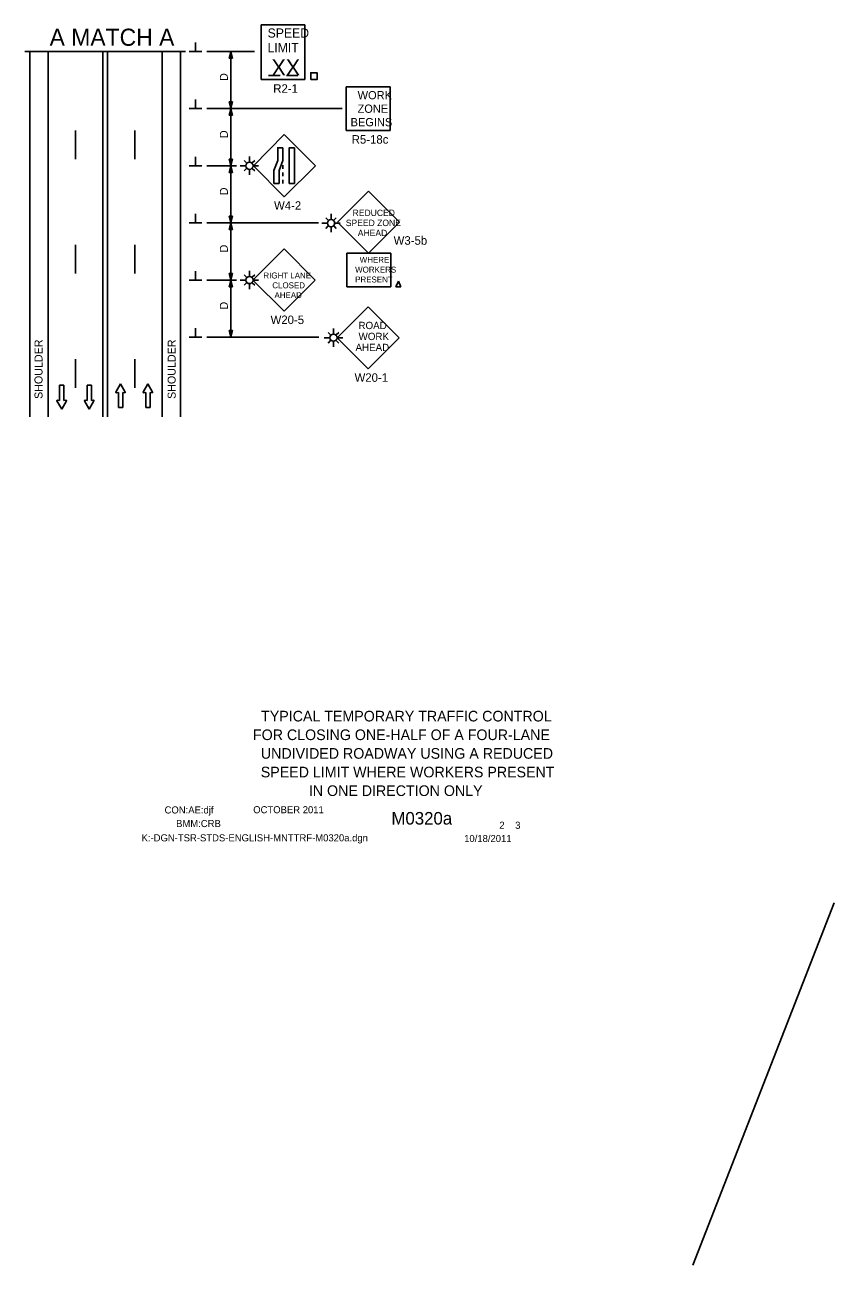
# Model space of a CAD drawing. Extents: x 16473 to 19504, y 4850 to 6923.
# Drawn here: x 17997 to 18706, y 5563 to 6648 of the extents above; entities that cross this region are included whole.
import ezdxf

# ---------------------------------------------------------------- set-up
doc = ezdxf.new("R2010")
doc.units = 0
for name, color, linetype in [('ALI_LEGAL_EX', 7, 'Continuous'), ('BORDER_SIGNAL_WO', 7, 'Continuous'), ('MT_SCRATCH_LEVEL_E', 7, 'Continuous'), ('PAVT_EDGE_EX', 7, 'Continuous'), ('TRAFFIC_SIGNS_PR', 7, 'Continuous'), ('TYPICAL_TEXT_DIMEN_PR', 7, 'Continuous')]:
    doc.layers.add(name, color=color, linetype=linetype)

msp = doc.modelspace()

# ---------------------------------------------------------------- linework, layer by layer
at = {"layer": 'ALI_LEGAL_EX'}
for points in [[(18041.7, 6555.4), (18041.7, 6530.4)], [(18093.7, 6555.4), (18093.7, 6530.4)], [(18041.7, 6455.4), (18041.7, 6430.4)], [(18093.7, 6455.4), (18093.7, 6430.4)], [(18041.7, 6355.4), (18041.7, 6330.4)], [(18093.7, 6355.4), (18093.7, 6330.4)]]:
    msp.add_lwpolyline(points, dxfattribs=at)
at = {"layer": 'MT_SCRATCH_LEVEL_E'}
for p, q in [((18031.5, 6332.7), (18027.8, 6332.7)), ((18027.8, 6332.7), (18027.8, 6319.4)), ((18031.5, 6332.7), (18027.8, 6332.7)), ((18027.8, 6332.7), (18027.8, 6319.4)), ((18031.5, 6319.4), (18031.5, 6332.7)), ((18031.5, 6319.4), (18031.5, 6332.7)), ((18055.7, 6332.7), (18051.9, 6332.7)), ((18051.9, 6332.7), (18051.9, 6319.4)), ((18055.7, 6332.7), (18051.9, 6332.7)), ((18051.9, 6332.7), (18051.9, 6319.4)), ((18055.7, 6319.4), (18055.7, 6332.7)), ((18055.7, 6319.4), (18055.7, 6332.7)), ((18081.2, 6333.9), (18077.1, 6326.7)), ((18081.2, 6333.9), (18077.1, 6326.7)), ((18077.5, 6326), (18079.3, 6326.3)), ((18077.5, 6326), (18079.3, 6326.3)), ((18079.3, 6326.3), (18079.3, 6313.1)), ((18079.3, 6326.3), (18079.3, 6313.1)), ((18085.3, 6326.7), (18081.2, 6333.9)), ((18085.3, 6326.7), (18081.2, 6333.9)), ((18083.1, 6313.1), (18083.1, 6326.3)), ((18083.1, 6326.3), (18084.8, 6326)), ((18083.1, 6313.1), (18083.1, 6326.3)), ((18083.1, 6326.3), (18084.8, 6326)), ((18105.1, 6333.9), (18101, 6326.7)), ((18105.1, 6333.9), (18101, 6326.7)), ((18101.5, 6326), (18103.3, 6326.3)), ((18101.5, 6326), (18103.3, 6326.3)), ((18103.3, 6326.3), (18103.3, 6313.1)), ((18103.3, 6326.3), (18103.3, 6313.1)), ((18109.2, 6326.7), (18105.1, 6333.9)), ((18109.2, 6326.7), (18105.1, 6333.9)), ((18107, 6313.1), (18107, 6326.3)), ((18107, 6326.3), (18108.8, 6326)), ((18107, 6313.1), (18107, 6326.3)), ((18107, 6326.3), (18108.8, 6326)), ((18025.5, 6319), (18029.7, 6311.8)), ((18025.5, 6319), (18029.7, 6311.8)), ((18027.8, 6319.4), (18026, 6319.7)), ((18027.8, 6319.4), (18026, 6319.7)), ((18029.7, 6311.8), (18033.8, 6319)), ((18029.7, 6311.8), (18033.8, 6319)), ((18033.3, 6319.7), (18031.5, 6319.4)), ((18033.3, 6319.7), (18031.5, 6319.4)), ((18049.7, 6319), (18053.8, 6311.8)), ((18049.7, 6319), (18053.8, 6311.8)), ((18051.9, 6319.4), (18050.2, 6319.7)), ((18051.9, 6319.4), (18050.2, 6319.7)), ((18053.8, 6311.8), (18057.9, 6319)), ((18053.8, 6311.8), (18057.9, 6319)), ((18057.5, 6319.7), (18055.7, 6319.4)), ((18057.5, 6319.7), (18055.7, 6319.4)), ((18079.3, 6313.1), (18083.1, 6313.1)), ((18079.3, 6313.1), (18083.1, 6313.1)), ((18103.3, 6313.1), (18107, 6313.1)), ((18103.3, 6313.1), (18107, 6313.1))]:
    msp.add_line(p, q, dxfattribs=at)
for centre, start, end in [((18077.5, 6326.5), 150.4248, 279.9638), ((18077.5, 6326.5), 150.4248, 279.9638), ((18084.9, 6326.5), 260.0362, 29.7731), ((18084.9, 6326.5), 260.0362, 29.7731), ((18101.4, 6326.5), 150.4248, 279.9638), ((18101.4, 6326.5), 150.4248, 279.9638), ((18108.8, 6326.5), 260.0362, 29.7731), ((18108.8, 6326.5), 260.0362, 29.7731), ((18025.9, 6319.2), 80.0362, 209.7731), ((18025.9, 6319.2), 80.0362, 209.7731), ((18033.4, 6319.2), 330.4248, 99.9638), ((18033.4, 6319.2), 330.4248, 99.9638), ((18050.1, 6319.2), 80.0362, 209.7731), ((18050.1, 6319.2), 80.0362, 209.7731), ((18057.5, 6319.2), 330.4248, 99.9638), ((18057.5, 6319.2), 330.4248, 99.9638)]:
    msp.add_arc(centre, 0.463, start, end, dxfattribs=at)
at = {"layer": 'PAVT_EDGE_EX'}
for p, q in [((18001.7, 6624.7), (18001.7, 6305.2)), ((18017.7, 6624.7), (18017.7, 6305.2)), ((18065.7, 6624.7), (18065.7, 6305.2)), ((18069.7, 6624.7), (18069.7, 6305.2)), ((18117.7, 6624.7), (18117.7, 6305.2)), ((18133.7, 6624.7), (18133.7, 6305.2))]:
    msp.add_line(p, q, dxfattribs=at)
at = {"layer": 'TRAFFIC_SIGNS_PR'}
for p, q in [((18204.2, 6648), (18242.6, 6648)), ((18204.2, 6600), (18204.2, 6648)), ((18204.2, 6648), (18242.6, 6648)), ((18204.2, 6600), (18204.2, 6648)), ((18242.6, 6600), (18242.6, 6648)), ((18242.6, 6600), (18242.6, 6648)), ((18204.2, 6600), (18242.6, 6600)), ((18204.2, 6600), (18242.6, 6600)), ((18210.8, 6603.6), (18220.9, 6603.6)), ((18226.3, 6603.6), (18236.3, 6603.6)), ((18278.7, 6555.4), (18278.7, 6593.8)), ((18278.7, 6593.8), (18317.1, 6593.8)), ((18317.1, 6555.4), (18317.1, 6593.8)), ((18278.7, 6555.4), (18317.1, 6555.4)), ((18224.5, 6551.9), (18197.4, 6524.7)), ((18251.7, 6524.7), (18224.5, 6551.9)), ((18194, 6528.3), (18194, 6532.8)), ((18190.8, 6524.7), (18186, 6524.7)), ((18191.5, 6527.2), (18189.4, 6529.3)), ((18191.5, 6522.2), (18189.4, 6520.1)), ((18194, 6516.8), (18194, 6521.2)), ((18196.5, 6527.2), (18198.6, 6529.3)), ((18196.5, 6522.2), (18198.6, 6520.1)), ((18197.1, 6524.7), (18202, 6524.7)), ((18197.4, 6524.7), (18224.5, 6497.6)), ((18223.3, 6525.2), (18223.3, 6522)), ((18224.5, 6497.6), (18251.7, 6524.7)), ((18223.3, 6518.8), (18223.3, 6515.6)), ((18223.3, 6512.4), (18223.3, 6509.2)), ((18298.2, 6502.6), (18271.1, 6475.4)), ((18325.4, 6475.4), (18298.2, 6502.6)), ((18262.9, 6477.1), (18260.7, 6479.2)), ((18265.4, 6478.1), (18265.4, 6482.6)), ((18267.9, 6477.1), (18270, 6479.2)), ((18262.2, 6474.5), (18257.4, 6474.5)), ((18262.9, 6472), (18260.7, 6469.9)), ((18265.4, 6466.6), (18265.4, 6471)), ((18267.9, 6472), (18270, 6469.9)), ((18268.5, 6474.5), (18273.4, 6474.5)), ((18271.1, 6475.4), (18298.2, 6448.2)), ((18298.2, 6448.2), (18325.4, 6475.4)), ((18224.3, 6451.9), (18197.1, 6424.7)), ((18251.4, 6424.7), (18224.3, 6451.9)), ((18279.2, 6448.1), (18317.6, 6448.1)), ((18279.2, 6418.8), (18279.2, 6448.1)), ((18317.6, 6418.8), (18317.6, 6448.1)), ((18190.8, 6424.7), (18186, 6424.7)), ((18191.5, 6427.3), (18189.4, 6429.4)), ((18194, 6428.3), (18194, 6432.8)), ((18196.5, 6427.3), (18198.6, 6429.4)), ((18197.1, 6424.7), (18202, 6424.7)), ((18197.1, 6424.7), (18224.3, 6397.6)), ((18224.3, 6397.6), (18251.4, 6424.7)), ((18191.5, 6422.2), (18189.4, 6420.1)), ((18194, 6416.8), (18194, 6421.2)), ((18196.5, 6422.2), (18198.6, 6420.1)), ((18279.2, 6418.8), (18317.6, 6418.8)), ((18297.8, 6401.4), (18270.7, 6374.3)), ((18325, 6374.3), (18297.8, 6401.4)), ((18267.5, 6377.8), (18267.5, 6382.3)), ((18264.4, 6374.3), (18259.5, 6374.3)), ((18265, 6376.8), (18262.9, 6378.9)), ((18265, 6371.7), (18262.9, 6369.6)), ((18267.5, 6366.3), (18267.5, 6370.7)), ((18270, 6376.8), (18272.1, 6378.9)), ((18270, 6371.7), (18272.1, 6369.6)), ((18270.7, 6374.3), (18297.8, 6347.1)), ((18270.7, 6374.3), (18275.6, 6374.3)), ((18297.8, 6347.1), (18325, 6374.3))]:
    msp.add_line(p, q, dxfattribs=at)
for points in [[(18247.6, 6600), (18253.2, 6600), (18253.2, 6606.1), (18247.6, 6606.1)], [(18223.3, 6540.5), (18223.3, 6529.3), (18219.9, 6520.4), (18219.9, 6509.2), (18215.4, 6509.2), (18215.4, 6520.4), (18218.8, 6529.3), (18218.8, 6540.5)], [(18233.4, 6540.5), (18233.4, 6509.2), (18228.9, 6509.2), (18228.9, 6540.5)]]:
    msp.add_lwpolyline(points, close=True, dxfattribs=at)
for points in [[(18324.3, 6423.8), (18322.1, 6418.8)], [(18322.1, 6418.8), (18324.3, 6423.8)], [(18326.5, 6418.8), (18324.3, 6423.8)], [(18324.3, 6423.8), (18326.5, 6418.8)], [(18322.1, 6418.8), (18326.5, 6418.8)], [(18326.5, 6418.8), (18322.1, 6418.8)]]:
    msp.add_lwpolyline(points, dxfattribs=at)
for centre in [(18194, 6524.7), (18265.4, 6474.5), (18194, 6424.7), (18267.5, 6374.3)]:
    msp.add_circle(centre, 3.15, dxfattribs=at)
at = {"layer": 'TYPICAL_TEXT_DIMEN_PR'}
for p, q in [((18146.8, 6624.7), (18146.8, 6632.5)), ((17997.4, 6624.7), (18138, 6624.7)), ((18152.4, 6624.7), (18141.2, 6624.7)), ((18198.3, 6624.7), (18156.7, 6624.7)), ((18176.1, 6618.8), (18177.7, 6624.7)), ((18177.7, 6618.8), (18176.1, 6618.8)), ((18177.7, 6624.7), (18177.7, 6574.7)), ((18177.7, 6624.7), (18179.3, 6618.8)), ((18179.3, 6618.8), (18177.7, 6618.8)), ((18146.8, 6574.7), (18146.8, 6582.5)), ((18177.7, 6574.7), (18176.1, 6580.5)), ((18176.1, 6580.5), (18177.7, 6580.5)), ((18177.7, 6580.5), (18179.3, 6580.5)), ((18179.3, 6580.5), (18177.7, 6574.7)), ((18152.4, 6574.7), (18141.2, 6574.7)), ((18275.2, 6574.7), (18156.7, 6574.7)), ((18176.1, 6568.8), (18177.7, 6574.7)), ((18177.7, 6568.8), (18176.1, 6568.8)), ((18177.7, 6574.7), (18179.3, 6568.8)), ((18177.7, 6574.7), (18177.7, 6524.7)), ((18179.3, 6568.8), (18177.7, 6568.8)), ((18146.8, 6524.7), (18146.8, 6532.5)), ((18152.4, 6524.7), (18141.2, 6524.7)), ((18182.7, 6524.7), (18156.7, 6524.7)), ((18177.7, 6524.7), (18176.1, 6530.5)), ((18176.1, 6530.5), (18177.7, 6530.5)), ((18176.1, 6518.8), (18177.7, 6524.7)), ((18177.7, 6530.5), (18179.3, 6530.5)), ((18179.3, 6530.5), (18177.7, 6524.7)), ((18177.7, 6524.7), (18177.7, 6474.7)), ((18177.7, 6524.7), (18179.3, 6518.8)), ((18177.7, 6518.8), (18176.1, 6518.8)), ((18179.3, 6518.8), (18177.7, 6518.8)), ((18146.8, 6474.7), (18146.8, 6482.5)), ((18177.7, 6474.7), (18176.1, 6480.5)), ((18176.1, 6480.5), (18177.7, 6480.5)), ((18177.7, 6480.5), (18179.3, 6480.5)), ((18179.3, 6480.5), (18177.7, 6474.7)), ((18152.4, 6474.7), (18141.2, 6474.7)), ((18254.3, 6474.7), (18156.7, 6474.7)), ((18176.1, 6468.8), (18177.7, 6474.7)), ((18177.7, 6468.8), (18176.1, 6468.8)), ((18177.7, 6474.7), (18177.7, 6424.7)), ((18177.7, 6474.7), (18179.3, 6468.8)), ((18179.3, 6468.8), (18177.7, 6468.8)), ((18152.4, 6424.7), (18141.2, 6424.7)), ((18146.8, 6424.7), (18146.8, 6432.5)), ((18182.7, 6424.7), (18156.7, 6424.7)), ((18177.7, 6424.7), (18176.1, 6430.5)), ((18176.1, 6430.5), (18177.7, 6430.5)), ((18176.1, 6418.8), (18177.7, 6424.7)), ((18177.7, 6430.5), (18179.3, 6430.5)), ((18179.3, 6430.5), (18177.7, 6424.7)), ((18177.7, 6424.7), (18177.7, 6374.7)), ((18177.7, 6424.7), (18179.3, 6418.8)), ((18177.7, 6418.8), (18176.1, 6418.8)), ((18179.3, 6418.8), (18177.7, 6418.8)), ((18146.8, 6374.7), (18146.8, 6382.5)), ((18177.7, 6374.7), (18176.1, 6380.5)), ((18176.1, 6380.5), (18177.7, 6380.5)), ((18177.7, 6380.5), (18179.3, 6380.5)), ((18179.3, 6380.5), (18177.7, 6374.7)), ((18152.4, 6374.7), (18141.2, 6374.7)), ((18254.8, 6374.7), (18156.7, 6374.7)), ((18705.8, 5880), (18582.1, 5563))]:
    msp.add_line(p, q, dxfattribs=at)

# ---------------------------------------------------------------- texts
at = {"layer": 'BORDER_SIGNAL_WO'}
for s, height, p in [('TYPICAL TEMPORARY TRAFFIC CONTROL', 9.3, (18204.2, 6038.6)), ('FOR CLOSING ONE-HALF OF A FOUR-LANE', 9.3, (18197.1, 6022.3)), ('UNDIVIDED ROADWAY USING A REDUCED', 9.3, (18204, 6006)), ('SPEED LIMIT WHERE WORKERS PRESENT', 9.3, (18203.9, 5989.7)), ('IN ONE DIRECTION ONLY', 9.3, (18246, 5973.4)), ('CON:AE:djf', 6.2, (18119.7, 5958.1)), ('    OCTOBER 2011    ', 6.2, (18188.1, 5958.3)), ('    M0320a   ', 11, (18301.9, 5948.4)), ('BMM:CRB   ', 6.2, (18129.8, 5946.2)), (' 2    3 ', 6.2, (18410.4, 5944.7)), ('K:-DGN-TSR-STDS-ENGLISH-MNTTRF-M0320a.dgn        ', 6.2, (18099.6, 5933.7)), ('10/18/2011    ', 6.2, (18381.9, 5933.1))]:
    msp.add_text(s, height=height, dxfattribs=at).set_placement(p)
at = {"layer": 'TRAFFIC_SIGNS_PR'}
for s, height, p in [('SPEED', 8, (18209.9, 6636.8)), ('SPEED', 8, (18209.9, 6636.8)), ('LIMIT', 8, (18209.8, 6624)), ('LIMIT', 8, (18209.8, 6624)), ('XX', 14.03, (18213.3, 6603.7)), ('R2-1', 7.44, (18214.9, 6588.5)), ('R2-1', 7.44, (18214.8, 6588.5)), ('WORK', 7.22, (18288.7, 6582.8)), ('ZONE', 7.22, (18288.6, 6571)), ('BEGINS', 7.22, (18282.5, 6559.2)), ('R5-18c', 7.44, (18283.5, 6544)), ('W4-2', 7.44, (18215.5, 6486.2)), ('SPEED ZONE', 5.6, (18278.3, 6471.9)), ('REDUCED', 5.6, (18284.3, 6480.7)), ('AHEAD', 5.6, (18288.8, 6463.1)), ('W3-5b', 7.44, (18320.2, 6455.6)), ('WHERE', 5.2, (18290.5, 6439.8)), ('WORKERS', 5.2, (18286.5, 6431.2)), ('RIGHT LANE', 5.2, (18206.2, 6426.1)), ('PRESENT', 5.2, (18286.5, 6422.6)), ('CLOSED', 5.2, (18214, 6417.5)), ('AHEAD', 5.2, (18215.9, 6408.9)), ('W20-5', 7.44, (18212.5, 6386.2)), ('ROAD', 6.4, (18289.4, 6381.8)), ('AHEAD', 6.4, (18286.8, 6362.6)), ('WORK', 6.4, (18289.5, 6372.2)), ('W20-1', 7.44, (18286, 6335.7))]:
    msp.add_text(s, height=height, dxfattribs=at).set_placement(p)
at = {"layer": 'TYPICAL_TEXT_DIMEN_PR'}
msp.add_text('A MATCH A', height=15, dxfattribs=at).set_placement((18019.1, 6629.6))
for s, p in [('D', (18175.1, 6598.9)), ('D', (18175.1, 6548.9)), ('D', (18175.1, 6498.9)), ('D', (18175.1, 6448.9)), ('D', (18175.1, 6398.9)), ('SHOULDER', (18012.9, 6320.7)), ('SHOULDER', (18129.4, 6320.7))]:
    msp.add_text(s, height=7, rotation=90, dxfattribs=at).set_placement(p)

doc.saveas('drawing.dxf')
